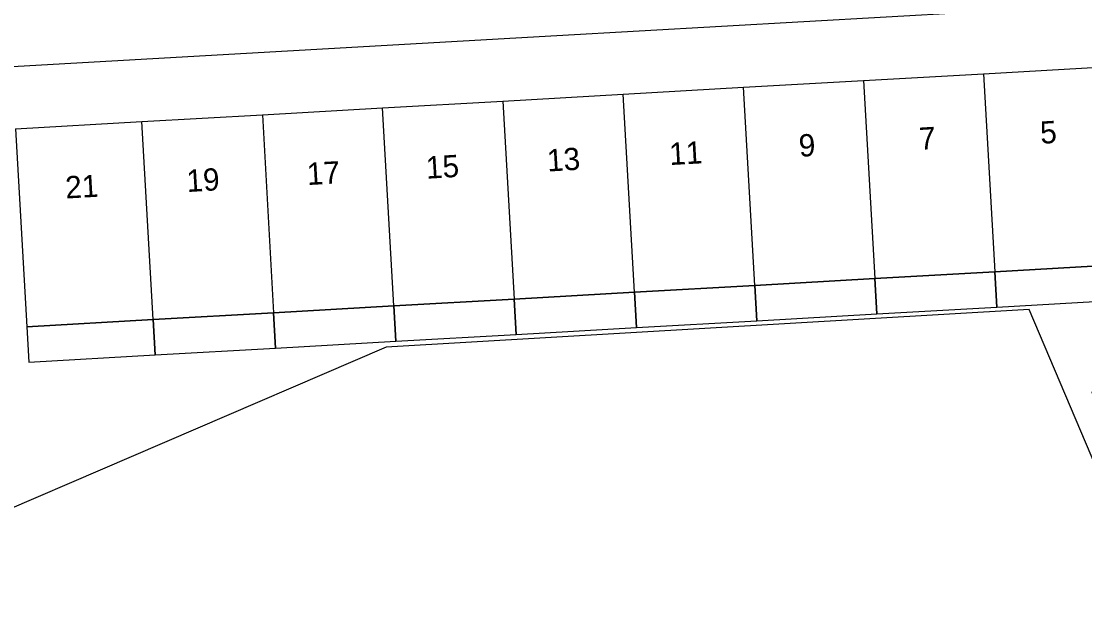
# Model space of a CAD drawing. Extents: x 155640 to 156810, y 382822 to 384046.
# Drawn here: x 156549.24 to 156597.01, y 383789.39 to 383815.25 of the extents above; entities that cross this region are included whole.
import ezdxf

# ---------------------------------------------------------------- set-up
doc = ezdxf.new("R2010")
doc.units = 0
for name, color, linetype in [('IMGEO_Lijnafwatering', 7, 'Continuous'), ('IMGEO_Pand', 7, 'Continuous'), ('IMGEO_Pand_nummerreeks', 7, 'Continuous'), ('IMGEO_Pand_overbouw', 7, 'Continuous'), ('IMGEO_Voetpad_open', 7, 'Continuous')]:
    doc.layers.add(name, color=color, linetype=linetype)

msp = doc.modelspace()

# ---------------------------------------------------------------- linework, layer by layer
at = {"layer": 'IMGEO_Lijnafwatering'}
for points in [[(156599.18, 383816.064), (156573.301, 383814.59)], [(156573.301, 383814.59), (156547.243, 383813.106)]]:
    msp.add_lwpolyline(points, dxfattribs=at)
at = {"layer": 'IMGEO_Pand'}
for points in [[(156619.306, 383814.422), (156620.197, 383799.996), (156597.327, 383798.583), (156599.334, 383793.861), (156599.125, 383793.772), (156601.176, 383788.945), (156600.332, 383788.586), (156594.507, 383802.295), (156565.638, 383800.613), (156545.7, 383792.039), (156538.063, 383809.8)], [(156587.068, 383812.588), (156592.458, 383812.894)], [(156592.458, 383812.894), (156597.896, 383813.204)], [(156592.458, 383812.894), (156592.965, 383803.991)], [(156581.685, 383812.282), (156587.068, 383812.588)], [(156587.068, 383812.588), (156587.575, 383803.685)], [(156570.867, 383811.666), (156576.272, 383811.973)], [(156576.272, 383811.973), (156581.685, 383812.282)], [(156576.779, 383803.073), (156576.272, 383811.973)], [(156582.192, 383803.38), (156581.685, 383812.282)], [(156565.465, 383811.359), (156570.867, 383811.666)], [(156570.867, 383811.666), (156571.374, 383802.766)], [(156554.66, 383810.744), (156560.07, 383811.052)], [(156560.07, 383811.052), (156565.465, 383811.359)], [(156560.07, 383811.052), (156560.576, 383802.153)], [(156565.971, 383802.459), (156565.465, 383811.359)], [(156548.99, 383810.421), (156554.66, 383810.744)], [(156555.167, 383801.846), (156554.66, 383810.744)], [(156548.99, 383810.421), (156549.495, 383801.524)], [(156592.965, 383803.991), (156598.403, 383804.3)], [(156587.575, 383803.685), (156592.965, 383803.991)], [(156576.779, 383803.073), (156582.192, 383803.38)], [(156582.192, 383803.38), (156587.575, 383803.685)], [(156571.374, 383802.766), (156576.779, 383803.073)], [(156560.576, 383802.153), (156565.971, 383802.459)], [(156565.971, 383802.459), (156571.374, 383802.766)], [(156555.167, 383801.846), (156560.576, 383802.153)], [(156549.495, 383801.524), (156555.167, 383801.846)]]:
    msp.add_lwpolyline(points, dxfattribs=at)
at = {"layer": 'IMGEO_Pand_overbouw'}
for points in [[(156592.965, 383803.991), (156593.055, 383802.41), (156598.493, 383802.72), (156598.403, 383804.3)], [(156592.965, 383803.991), (156587.575, 383803.685), (156587.665, 383802.103), (156593.055, 383802.41)], [(156576.779, 383803.073), (156576.869, 383801.489), (156582.283, 383801.797), (156582.192, 383803.38)], [(156587.575, 383803.685), (156582.192, 383803.38), (156582.283, 383801.797), (156587.665, 383802.103)], [(156571.374, 383802.766), (156571.464, 383801.181), (156576.869, 383801.489), (156576.779, 383803.073)], [(156560.576, 383802.153), (156560.667, 383800.566), (156566.062, 383800.873), (156565.971, 383802.459)], [(156571.374, 383802.766), (156565.971, 383802.459), (156566.062, 383800.873), (156571.464, 383801.181)], [(156560.576, 383802.153), (156555.167, 383801.846), (156555.257, 383800.258), (156560.667, 383800.566)], [(156549.495, 383801.524), (156549.585, 383799.935), (156555.257, 383800.258), (156555.167, 383801.846)]]:
    msp.add_lwpolyline(points, close=True, dxfattribs=at)
at = {"layer": 'IMGEO_Voetpad_open'}
msp.add_lwpolyline([(156549.495, 383801.524), (156549.585, 383799.935), (156555.257, 383800.258), (156560.667, 383800.566), (156566.062, 383800.873), (156571.464, 383801.181), (156576.869, 383801.489), (156582.283, 383801.797), (156587.665, 383802.103), (156593.055, 383802.41), (156598.493, 383802.72), (156603.914, 383803.029), (156609.671, 383803.357), (156609.581, 383804.935)], dxfattribs=at)

# ---------------------------------------------------------------- texts
at = {"layer": 'IMGEO_Pand_nummerreeks'}
for s, rotation, p in [('7', 3.414, (156589.599, 383809.47)), ('5', 3.3677, (156595.033, 383809.744)), ('9', 3.1519, (156584.191, 383809.16)), ('13', 3.4776, (156572.885, 383808.494)), ('11', 3.1519, (156578.372, 383808.787)), ('15', 3.414, (156567.446, 383808.172)), ('19', 3.4297, (156556.692, 383807.574)), ('17', 3.1958, (156562.096, 383807.888)), ('21', 3.2646, (156551.246, 383807.283))]:
    msp.add_text(s, height=1, rotation=rotation, dxfattribs=at).set_placement(p)

doc.saveas('drawing.dxf')
